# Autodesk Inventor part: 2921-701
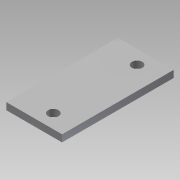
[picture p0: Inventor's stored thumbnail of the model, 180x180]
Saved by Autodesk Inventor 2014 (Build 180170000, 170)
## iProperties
Company: NHTSA/VRTC
Created: 2012-11
Part Number: 2921-701
Material: Steel, Mild
Document SubType Name: Modeling
Designer: Mike Vanvoorhis
Density: 7.86 g/cm^3
Project: CHILD SIDE IMPACT SLED
Description: LIGHT TRAP MOUNT BASE PLATE
Mass: 2003.93 g
Surface Area: 494.122 cm^2
Volume: 254.953 cm^3
Appearance: Steel
Stock Number: BAR 101.6 (4") x 12.7 (1/2") x 203.2 (8")
Author: Dave Walker
Title: Light Trap Mount Base Plate
Subject: Child Side Impact Sled
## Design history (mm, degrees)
sketch "Sketch1"
  geometry: L1 (0, 0)-(12.7, 0); L2 (12.7, 0)-(12.7, -203.2); L3 (12.7, -203.2)-(0, -203.2); L4 (0, -203.2)-(0, 0)
  constraints: 8 end point, 2 parallel, 1 horizontal, 1 perpendicular
  dimensions: "d0" = 12.7 distance of L2.end L3.end; "d1" = 203.2 distance of L1.end L2.end
extrude "Extrusion1" new body sketch "Sketch1" distance "d2" = 101.6; taper "d3" = 0 deg
sketch "Sketch2"
  geometry: L1 (0, 0)-(101.6, 0) reference; L2 (101.6, 203.2)-(101.6, 0) reference; L3 (0, 203.2)-(101.6, 203.2) reference; L4 (60.325, 0)-(60.325, 203.2); 2 further points
  constraints: 4 point on line, 2 end point, 1 perpendicular
  dimensions: "d4" = 41.275 distance between parallel lines of L2 L4; "d5" = 152.4 distance of point (60.325, 177.8) point (60.325, 25.4); "d6" = 25.4 distance from line of L1 point (60.325, 25.4)
hole "Hole1" sketch "Sketch2" at (60.325, 25.4), (60.325, 177.8) diameter "d7" = 19.05; stored, may be unused: countersink angle "d11" = 82 deg, drill point angle "d13" = 118 deg; dims "d8" = 19.05, "d9" = 9.525, "d10" = 6.35, "d12" = 25.4
body "Solid1"
